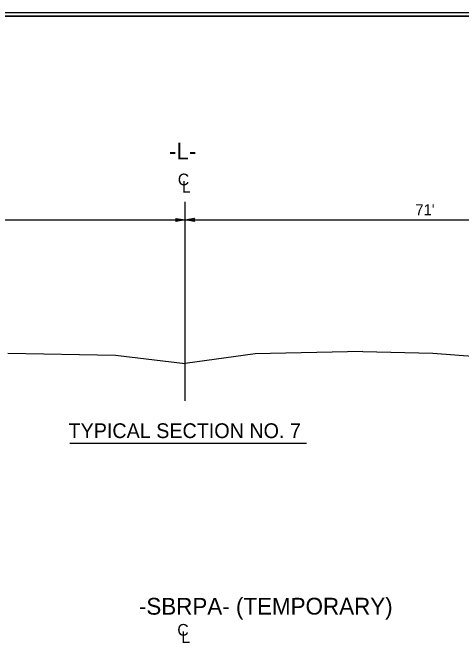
# Model space of a CAD drawing. Extents: x 2241081 to 2251104, y 658534 to 663427.
# Drawn here: x 2248414.7 to 2248749.5, y 660227 to 660704.3 of the extents above; entities that cross this region are included whole.
import ezdxf

# ---------------------------------------------------------------- set-up
doc = ezdxf.new("R2010")
doc.units = 0
for name, color, linetype in [('Old_Level_2', 7, 'Continuous'), ('Prop Dimension Text', 7, 'Continuous'), ('Sheet Plan CELL', 7, 'Continuous'), ('Sheet Plot Border Inside CELL', 7, 'Continuous'), ('Typical Terminator CELL', 7, 'Continuous'), ('Typical Text Centerline CELL', 7, 'Continuous'), ('Typical Text Label CELL', 7, 'Continuous')]:
    doc.layers.add(name, color=color, linetype=linetype)

msp = doc.modelspace()

# ---------------------------------------------------------------- linework, layer by layer
at = {"layer": 'Old_Level_2'}
for p, q in [((2248410.97, 660450.27), (2248491.33, 660448.65)), ((2248491.33, 660448.65), (2248543.47, 660442.62)), ((2248595.61, 660449.65), (2248543.47, 660442.62)), ((2248675.97, 660451.37), (2248595.61, 660449.65)), ((2248675.97, 660451.37), (2248728.38, 660450.31)), ((2248728.38, 660450.31), (2248783.43, 660445.97))]:
    msp.add_line(p, q, dxfattribs=at)
at = {"layer": 'Prop Dimension Text'}
for p, q in [((2248210.91, 660549.62), (2248543.41, 660549.62)), ((2248543.41, 660549.62), (2248888.41, 660549.62))]:
    msp.add_line(p, q, dxfattribs=at)
at = {"layer": 'Sheet Plan CELL'}
for points in [[(2247801.99, 659651.78), (2247801.97, 660701.75), (2249101.96, 660701.79), (2249101.97, 660551.73), (2249302.01, 660551.71), (2249302.01, 659651.78)], [(2249302.03, 660701.78), (2247801.99, 660701.78), (2247801.99, 659651.78), (2249302.01, 659651.78)]]:
    msp.add_lwpolyline(points, close=True, dxfattribs=at)
at = {"layer": 'Sheet Plot Border Inside CELL'}
msp.add_lwpolyline([(2247648.51, 659649.27), (2249314.49, 659649.28), (2249314.51, 660704.26), (2247648.51, 660704.27)], close=True, dxfattribs=at)
at = {"layer": 'Typical Terminator CELL'}
for points in [[(2248536.38, 660550.83), (2248543.41, 660549.62), (2248536.34, 660548.37), (2248537.24, 660549.62)], [(2248550.44, 660548.41), (2248543.41, 660549.62), (2248550.48, 660550.87), (2248549.58, 660549.62)]]:
    msp.add_lwpolyline(points, close=True, dxfattribs=at)
at = {"layer": 'Typical Text Centerline CELL'}
msp.add_line((2248543.49, 660414.64), (2248543.4, 660563.2), dxfattribs=at)
at = {"layer": 'Typical Text Label CELL'}
msp.add_line((2248457.21, 660383.16), (2248633.88, 660383.16), dxfattribs=at)

# ---------------------------------------------------------------- texts
at = {"layer": 'Prop Dimension Text'}
for s, height, p in [('-L-', 12.5, (2248531.32, 660594.83)), ("71'", 8.25, (2248715.25, 660553.08)), ('-SBRPA- (TEMPORARY)', 12.5, (2248508.86, 660255.04))]:
    msp.add_text(s, height=height, rotation=0.0349, dxfattribs=at).set_placement(p)
at = {"layer": 'Typical Text Centerline CELL'}
for s, rotation, p in [('C', 0.0349, (2248537.93, 660575.47)), ('L', 359.9818, (2248540.96, 660569.97)), ('C', 0.0349, (2248537.55, 660239.33)), ('L', 359.9818, (2248540.58, 660233.83))]:
    msp.add_text(s, height=8.76, rotation=rotation, dxfattribs=at).set_placement(p)
at = {"layer": 'Typical Text Label CELL'}
msp.add_text('TYPICAL SECTION NO. 7', height=11.0106, dxfattribs=at).set_placement((2248456.34, 660386.85))

doc.saveas('drawing.dxf')
